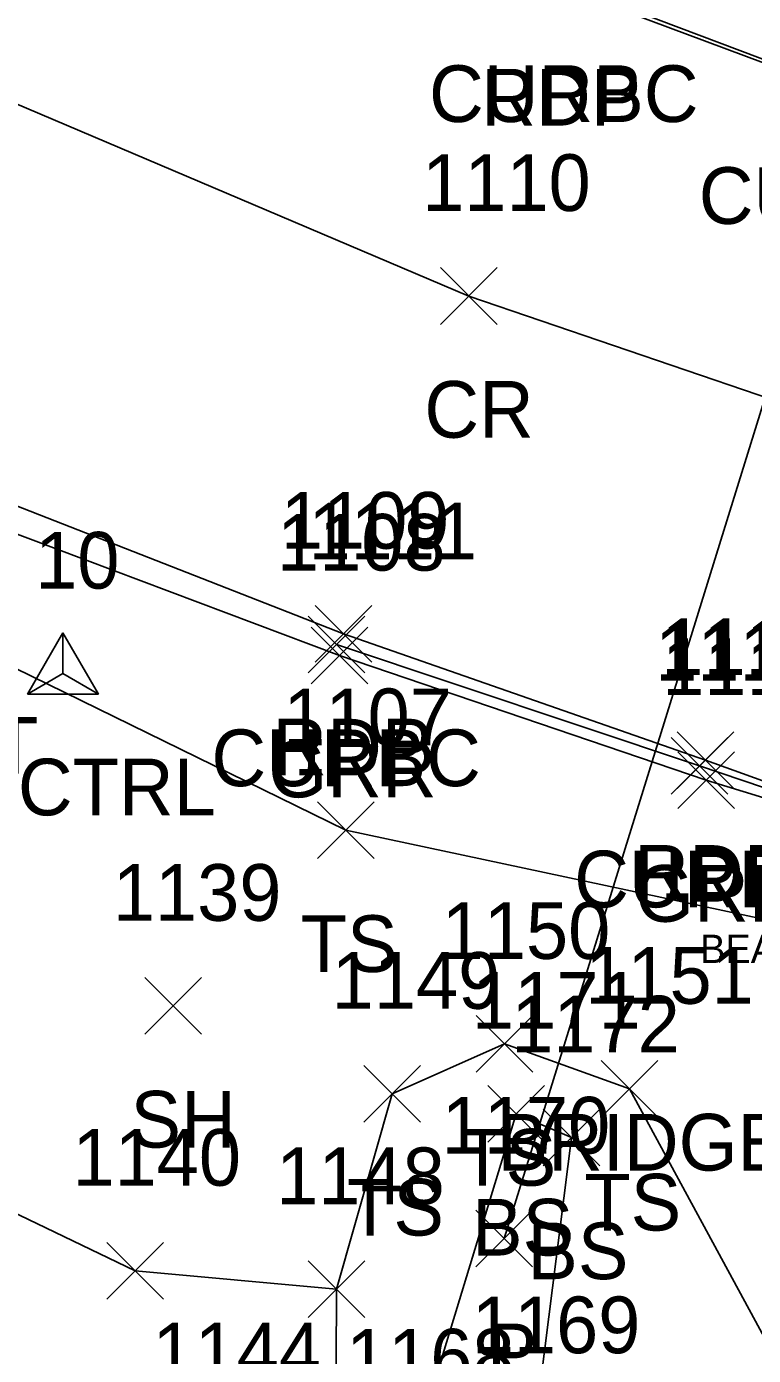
# Model space of a CAD drawing. Extents: x 1761340 to 1763889, y 696770 to 706023.
# Drawn here: x 1761564.66 to 1761590.31, y 700831.65 to 700878.53 of the extents above; entities that cross this region are included whole.
import ezdxf

# ---------------------------------------------------------------- set-up
doc = ezdxf.new("R2010")
doc.units = 0
for name, color, linetype in [('B_C', 7, 'Continuous'), ('C_A', 7, 'Continuous'), ('C_C', 7, 'Continuous'), ('C_I', 7, 'Continuous'), ('CPSM', 7, 'Continuous'), ('D_A', 7, 'Continuous'), ('D_I', 7, 'Continuous'), ('D_TIC', 7, 'Continuous'), ('DCP', 7, 'Continuous'), ('L_A', 7, 'Continuous'), ('L_I', 7, 'Continuous'), ('L_TIC', 7, 'Continuous'), ('LABL', 7, 'Continuous'), ('LELB', 7, 'Continuous'), ('P_A', 7, 'Continuous'), ('P_I', 7, 'Continuous'), ('P_TIC', 7, 'Continuous'), ('PET', 7, 'Continuous'), ('PRC', 7, 'Continuous'), ('R_A', 7, 'Continuous'), ('R_I', 7, 'Continuous'), ('R_TIC', 7, 'Continuous'), ('RC', 7, 'Continuous'), ('RGR', 7, 'Continuous'), ('S_C', 7, 'Continuous')]:
    doc.layers.add(name, color=color, linetype=linetype)

msp = doc.modelspace()

# ---------------------------------------------------------------- linework, layer by layer
at = {"layer": 'CPSM'}
for p, q in [((1761564.692, 700854.983), (1761565.942, 700857.148)), ((1761567.192, 700854.983), (1761565.942, 700857.148)), ((1761565.942, 700855.704), (1761565.942, 700857.148)), ((1761564.692, 700854.983), (1761565.942, 700855.704)), ((1761565.942, 700855.704), (1761565.942, 700855.704)), ((1761565.942, 700855.704), (1761567.192, 700854.983)), ((1761564.692, 700854.983), (1761567.192, 700854.983))]:
    msp.add_line(p, q, dxfattribs=at)
at = {"layer": 'D_TIC'}
for points in [[(1761580.514, 700834.771), (1761582.514, 700836.771)], [(1761582.514, 700834.771), (1761580.514, 700836.771)]]:
    msp.add_lwpolyline(points, dxfattribs=at)
at = {"layer": 'DCP'}
msp.add_lwpolyline([(1761581.514, 700835.771), (1761593.381, 700874.024)], dxfattribs=at)
at = {"layer": 'L_TIC'}
for points in [[(1761574.919, 700849.178), (1761576.919, 700851.178)], [(1761576.919, 700849.178), (1761574.919, 700851.178)], [(1761568.835, 700842.983), (1761570.835, 700844.983)], [(1761570.835, 700842.983), (1761568.835, 700844.983)], [(1761580.517, 700841.64), (1761582.517, 700843.64)], [(1761582.517, 700841.64), (1761580.517, 700843.64)], [(1761576.556, 700839.879), (1761578.556, 700841.879)], [(1761578.556, 700839.879), (1761576.556, 700841.879)], [(1761584.93, 700840.056), (1761586.93, 700842.056)], [(1761586.93, 700840.056), (1761584.93, 700842.056)], [(1761580.934, 700839.174), (1761582.934, 700841.174)], [(1761582.934, 700839.174), (1761580.934, 700841.174)], [(1761582.885, 700838.339), (1761584.885, 700840.339)], [(1761584.885, 700838.339), (1761582.885, 700840.339)], [(1761582.885, 700838.339), (1761584.885, 700840.339)], [(1761584.885, 700838.339), (1761582.885, 700840.339)], [(1761567.486, 700833.637), (1761569.486, 700835.637)], [(1761569.486, 700833.637), (1761567.486, 700835.637)], [(1761574.59, 700832.986), (1761576.59, 700834.986)], [(1761576.59, 700832.986), (1761574.59, 700834.986)], [(1761574.59, 700832.986), (1761576.59, 700834.986)], [(1761576.59, 700832.986), (1761574.59, 700834.986)]]:
    msp.add_lwpolyline(points, dxfattribs=at)
at = {"layer": 'LABL'}
msp.add_lwpolyline([(1761502.66, 700832.329), (1761503.71, 700859.788), (1761494.962, 700875.248), (1761503.397, 700881.503), (1761510.453, 700875.51), (1761532.731, 700858.631), (1761547.414, 700844.769), (1761568.486, 700834.637), (1761575.59, 700833.986)], dxfattribs=at)
at = {"layer": 'LELB'}
for points in [[(1761502.66, 700832.329), (1761493.702, 700859.399), (1761488.552, 700870.199), (1761483.139, 700875.038), (1761493.666, 700887.924), (1761503.531, 700888.769), (1761525.808, 700875.875), (1761549.641, 700863.05), (1761575.919, 700850.178), (1761596.958, 700845.698)], [(1761577.539, 700801.73), (1761575.514, 700815.635), (1761575.59, 700833.986), (1761577.556, 700840.879), (1761581.517, 700842.64), (1761585.93, 700841.056), (1761592.344, 700829.236), (1761595.734, 700820.511), (1761594.635, 700804.09)], [(1761610.621, 700781.935), (1761590.608, 700792.381), (1761586.211, 700801.285), (1761584.094, 700814.53), (1761578.1, 700827.586), (1761581.934, 700840.174), (1761583.885, 700839.339)], [(1761611.543, 700784.306), (1761591.202, 700796.53), (1761588.305, 700801.978), (1761588.217, 700817.541), (1761582.546, 700828.727), (1761583.885, 700839.339)]]:
    msp.add_lwpolyline(points, dxfattribs=at)
at = {"layer": 'P_TIC'}
for points in [[(1761579.259, 700868.028), (1761581.259, 700870.028)], [(1761581.259, 700868.028), (1761579.259, 700870.028)], [(1761574.841, 700856.112), (1761576.841, 700858.112)], [(1761576.841, 700856.112), (1761574.841, 700858.112)], [(1761587.612, 700851.655), (1761589.612, 700853.655)], [(1761589.612, 700851.655), (1761587.612, 700853.655)]]:
    msp.add_lwpolyline(points, dxfattribs=at)
at = {"layer": 'PET'}
msp.add_lwpolyline([(1761551.015, 700866.825), (1761575.841, 700857.112), (1761588.612, 700852.655), (1761598.439, 700849.106), (1761600.688, 700862.06), (1761602.26, 700873.054), (1761592.745, 700876.48), (1761583.21, 700880.042), (1761565.694, 700887.32), (1761551.927, 700894.01)], dxfattribs=at)
at = {"layer": 'PRC'}
msp.add_lwpolyline([(1761371.661, 701058.145), (1761390.633, 701031.264), (1761404.648, 701011.453), (1761424.14, 700985.995), (1761443.925, 700962.202), (1761463.212, 700942.493), (1761486.68, 700921.951), (1761508.059, 700906.418), (1761533.506, 700890.818), (1761557.035, 700878.891), (1761580.259, 700869.028), (1761600.688, 700862.06)], dxfattribs=at)
at = {"layer": 'R_TIC'}
for points in [[(1761574.597, 700855.734), (1761576.597, 700857.734)], [(1761576.597, 700855.734), (1761574.597, 700857.734)], [(1761574.698, 700855.339), (1761576.698, 700857.339)], [(1761576.698, 700855.339), (1761574.698, 700857.339)], [(1761587.398, 700851.457), (1761589.398, 700853.457)], [(1761589.398, 700851.457), (1761587.398, 700853.457)], [(1761587.643, 700850.951), (1761589.643, 700852.951)], [(1761589.643, 700850.951), (1761587.643, 700852.951)]]:
    msp.add_lwpolyline(points, dxfattribs=at)
at = {"layer": 'RC'}
for points in [[(1761602.258, 700873.311), (1761592.794, 700876.572), (1761583.275, 700880.167), (1761565.849, 700887.443)], [(1761575.597, 700856.734), (1761588.398, 700852.457), (1761598.273, 700849.106)]]:
    msp.add_lwpolyline(points, dxfattribs=at)
at = {"layer": 'RGR'}
msp.add_lwpolyline([(1761493.647, 700890.305), (1761499.496, 700890.829), (1761506.08, 700888.951), (1761526.771, 700877.632), (1761550.687, 700865.756), (1761575.698, 700856.339), (1761588.643, 700851.951), (1761598.079, 700849.055)], dxfattribs=at)

# ---------------------------------------------------------------- texts
at = {"layer": 'B_C'}
msp.add_text('BEAM DIMENSIONS 0.9W X 2.5H', height=1, dxfattribs=at).set_placement((1761588.427, 700845.494))
at = {"layer": 'C_A'}
msp.add_text('HVCTRL', height=2, dxfattribs=at).set_placement((1761560.635, 700850.704))
at = {"layer": 'C_C'}
msp.add_text('NAIL IN TOP OF GRR POST', height=2, dxfattribs=at).set_placement((1761530.297, 700852.173))
at = {"layer": 'C_I'}
msp.add_text('10', height=2, dxfattribs=at).set_placement((1761564.958, 700858.704))
at = {"layer": 'D_A'}
msp.add_text('P', height=2, dxfattribs=at).set_placement((1761580.892, 700830.771))
at = {"layer": 'D_I'}
msp.add_text('1170', height=2, dxfattribs=at).set_placement((1761579.302, 700838.771))
at = {"layer": 'L_A'}
for s, p in [('TS', (1761574.329, 700845.178)), ('SH', (1761568.323, 700838.983)), ('TS', (1761579.927, 700837.64)), ('TS', (1761584.339, 700836.056)), ('TS', (1761575.966, 700835.879)), ('BS', (1761580.375, 700835.174)), ('BS', (1761582.326, 700834.339)), ('BS', (1761582.326, 700834.339))]:
    msp.add_text(s, height=2, dxfattribs=at).set_placement(p)
at = {"layer": 'L_I'}
for s, p in [('1107', (1761573.715, 700853.178)), ('1139', (1761567.701, 700846.983)), ('1150', (1761579.305, 700845.64)), ('1151', (1761584.371, 700844.056)), ('1149', (1761575.423, 700843.879)), ('1171', (1761580.375, 700843.174)), ('1172', (1761581.759, 700842.339)), ('1172', (1761581.759, 700842.339)), ('1140', (1761566.274, 700837.637)), ('1148', (1761573.465, 700836.986)), ('1148', (1761573.465, 700836.986)), ('1169', (1761580.366, 700831.727)), ('1144', (1761569.097, 700830.801)), ('1168', (1761575.927, 700830.586))]:
    msp.add_text(s, height=2, dxfattribs=at).set_placement(p)
at = {"layer": 'P_A'}
for s, p in [('RDP', (1761580.698, 700875.042)), ('CR', (1761578.692, 700864.028)), ('RDP', (1761573.329, 700852.112)), ('RDP', (1761586.101, 700847.655))]:
    msp.add_text(s, height=2, dxfattribs=at).set_placement(p)
at = {"layer": 'P_I'}
for s, p in [('1110', (1761578.614, 700872.028)), ('1109', (1761573.629, 700860.112)), ('1113', (1761587.054, 700855.655))]:
    msp.add_text(s, height=2, dxfattribs=at).set_placement(p)
at = {"layer": 'R_A'}
for s, p in [('CURBC', (1761578.858, 700875.167)), ('CURBC', (1761588.376, 700871.572)), ('CURBC', (1761571.179, 700851.734)), ('GRR', (1761573.186, 700851.339)), ('CURBC', (1761583.981, 700847.457)), ('GRR', (1761586.132, 700846.951))]:
    msp.add_text(s, height=2, dxfattribs=at).set_placement(p)
at = {"layer": 'R_I'}
for s, p in [('1111', (1761574.605, 700859.734)), ('1108', (1761573.493, 700859.339)), ('1112', (1761586.839, 700855.457)), ('1114', (1761587.085, 700854.951))]:
    msp.add_text(s, height=2, dxfattribs=at).set_placement(p)
at = {"layer": 'S_C'}
msp.add_text('BRIDGE 6 VT 2B', height=2, dxfattribs=at).set_placement((1761581.276, 700838.172))

doc.saveas('drawing.dxf')
